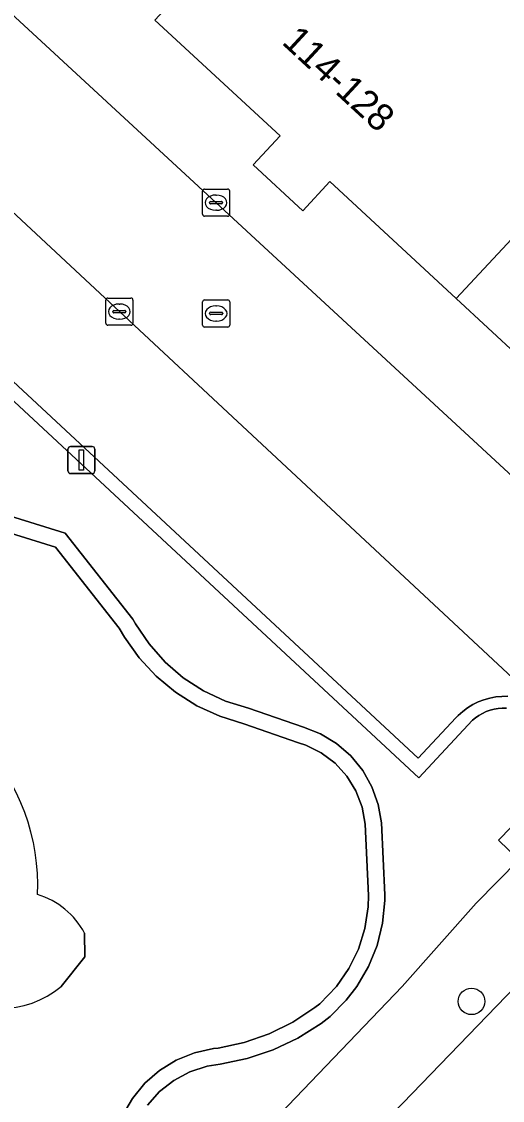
# Model space of a CAD drawing. Extents: x 159217 to 160349, y 381246 to 382172.
# Drawn here: x 159843.78 to 159861.49, y 381745.8 to 381785.53 of the extents above; entities that cross this region are included whole.
import ezdxf

# ---------------------------------------------------------------- set-up
doc = ezdxf.new("R2010")
doc.units = 0
for name, color, linetype in [('IMGEO_Boom', 7, 'Continuous'), ('IMGEO_Groenvoorziening', 7, 'Continuous'), ('IMGEO_Haag', 7, 'Continuous'), ('IMGEO_Kolk', 7, 'Continuous'), ('IMGEO_Lichtmast', 7, 'Continuous'), ('IMGEO_Pand', 7, 'Continuous'), ('IMGEO_Pand_nummerreeks', 7, 'Continuous'), ('IMGEO_Parkeervlak_open', 7, 'Continuous'), ('IMGEO_Rijbaan_lokaal_gesloten', 7, 'Continuous'), ('IMGEO_Rijbaan_lokaal_open', 7, 'Continuous'), ('IMGEO_Rioolput', 7, 'Continuous'), ('IMGEO_Voetpad_halfverhard', 7, 'Continuous'), ('IMGEO_Voetpad_open', 7, 'Continuous')]:
    doc.layers.add(name, color=color, linetype=linetype)

msp = doc.modelspace()

# ---------------------------------------------------------------- linework, layer by layer
at = {"layer": 'IMGEO_Boom'}
msp.add_circle((159860.355, 381749.447), 0.489, dxfattribs=at)
at = {"layer": 'IMGEO_Groenvoorziening'}
for points in [[(159861.641, 381760.247), (159861.488, 381760.248), (159861.335, 381760.235), (159861.185, 381760.209), (159861.037, 381760.17), (159860.893, 381760.117), (159860.755, 381760.052), (159860.623, 381759.975), (159860.499, 381759.887), (159860.395, 381759.799), (159858.417, 381757.678), (159829.839, 381784.238)], [(159848.422, 381745.62), (159848.866, 381746.122), (159849.392, 381746.537), (159849.984, 381746.851), (159850.622, 381747.055), (159851.095, 381747.13), (159852.085, 381747.338), (159853.043, 381747.661), (159853.956, 381748.096), (159854.811, 381748.635), (159855.152, 381748.893), (159855.743, 381749.491), (159856.133, 381750), (159856.558, 381750.727), (159856.874, 381751.506), (159857.077, 381752.322), (159857.162, 381753.159), (159857.164, 381753.365), (159857.033, 381756.016), (159856.919, 381756.699), (159856.688, 381757.352), (159856.349, 381757.955), (159855.911, 381758.491), (159855.387, 381758.944), (159854.792, 381759.299), (159854.166, 381759.541), (159852.136, 381760.243), (159851.289, 381760.508), (159850.485, 381760.886), (159849.739, 381761.367), (159849.065, 381761.945), (159848.476, 381762.609), (159847.98, 381763.346), (159847.88, 381763.526), (159845.383, 381766.692), (159839.65, 381768.475)], [(159839.65, 381768.475), (159845.383, 381766.692), (159847.88, 381763.526), (159847.98, 381763.346), (159848.476, 381762.609), (159849.065, 381761.945), (159849.739, 381761.367), (159850.485, 381760.886), (159851.289, 381760.508), (159852.136, 381760.243), (159854.166, 381759.541), (159854.792, 381759.299), (159855.387, 381758.944), (159855.911, 381758.491), (159856.349, 381757.955), (159856.688, 381757.352), (159856.919, 381756.699), (159857.033, 381756.016), (159857.164, 381753.365), (159857.162, 381753.159), (159857.077, 381752.322), (159856.874, 381751.506), (159856.558, 381750.727), (159856.133, 381750), (159855.743, 381749.491), (159855.152, 381748.893), (159854.811, 381748.635), (159853.956, 381748.096), (159853.043, 381747.661), (159852.085, 381747.338), (159851.095, 381747.13), (159850.622, 381747.055), (159849.984, 381746.851), (159849.392, 381746.537), (159848.866, 381746.122), (159848.422, 381745.62)], [(159847.504, 381745.245), (159847.864, 381745.87), (159848.322, 381746.428), (159848.866, 381746.902), (159849.48, 381747.279), (159850.149, 381747.55), (159850.854, 381747.706), (159851.022, 381747.725), (159851.976, 381747.93), (159852.897, 381748.25), (159853.772, 381748.68), (159854.588, 381749.215), (159854.767, 381749.353), (159855.386, 381750), (159855.839, 381750.657), (159856.189, 381751.373), (159856.427, 381752.135), (159856.548, 381752.923), (159856.564, 381753.349), (159856.434, 381755.977), (159856.323, 381756.605), (159856.096, 381757.202), (159855.762, 381757.745), (159855.332, 381758.217), (159854.822, 381758.6), (159854.249, 381758.881), (159853.985, 381758.969), (159851.967, 381759.666), (159851.082, 381759.945), (159850.241, 381760.335), (159849.456, 381760.831), (159848.743, 381761.424), (159848.111, 381762.103), (159847.573, 381762.859), (159847.377, 381763.195), (159845.027, 381766.174), (159839.528, 381767.885)], [(159839.528, 381767.885), (159845.027, 381766.174), (159847.377, 381763.195), (159847.573, 381762.859), (159848.111, 381762.103), (159848.743, 381761.424), (159849.456, 381760.831), (159850.241, 381760.335), (159851.082, 381759.945), (159851.967, 381759.666), (159853.985, 381758.969), (159854.249, 381758.881), (159854.822, 381758.6), (159855.332, 381758.217), (159855.762, 381757.745), (159856.096, 381757.202), (159856.323, 381756.605), (159856.434, 381755.977), (159856.564, 381753.349), (159856.548, 381752.923), (159856.427, 381752.135), (159856.189, 381751.373), (159855.839, 381750.657), (159855.386, 381750), (159854.767, 381749.353), (159854.588, 381749.215), (159853.772, 381748.68), (159852.897, 381748.25), (159851.976, 381747.93), (159851.022, 381747.725), (159850.854, 381747.706), (159850.149, 381747.55), (159849.48, 381747.279), (159848.866, 381746.902), (159848.322, 381746.428), (159847.864, 381745.87), (159847.504, 381745.245)], [(159836.763, 381728.06), (159857.805, 381750), (159860.522, 381753.058), (159862.102, 381754.657), (159861.343, 381755.378), (159864.2, 381758.302)], [(159846.104, 381751.957), (159846.111, 381751.081), (159845.243, 381750)]]:
    msp.add_lwpolyline(points, dxfattribs=at)
for centre, radius, start, end in [((159836.67, 381753.73), 7.707, 357.3917, 89.0761), ((159843.535, 381750.592), 2.909, 27.9855, 73.3386), ((159842.981, 381752.704), 3.525, 230.0948, 309.9052)]:
    msp.add_arc(centre, radius, start, end, dxfattribs=at)
at = {"layer": 'IMGEO_Haag'}
for points in [[(159848.422, 381745.62), (159848.866, 381746.122), (159849.392, 381746.537), (159849.984, 381746.851), (159850.622, 381747.055), (159851.095, 381747.13), (159852.085, 381747.338), (159853.043, 381747.661), (159853.956, 381748.096), (159854.811, 381748.635), (159855.152, 381748.893), (159855.743, 381749.491), (159856.133, 381750), (159856.558, 381750.727), (159856.874, 381751.506), (159857.077, 381752.322), (159857.162, 381753.159), (159857.164, 381753.365), (159857.033, 381756.016), (159856.919, 381756.699), (159856.688, 381757.352), (159856.349, 381757.955), (159855.911, 381758.491), (159855.387, 381758.944), (159854.792, 381759.299), (159854.166, 381759.541), (159852.136, 381760.243), (159851.289, 381760.508), (159850.485, 381760.886), (159849.739, 381761.367), (159849.065, 381761.945), (159848.476, 381762.609), (159847.98, 381763.346), (159847.88, 381763.526), (159845.383, 381766.692), (159839.65, 381768.475)], [(159839.528, 381767.885), (159845.027, 381766.174), (159847.377, 381763.195), (159847.573, 381762.859), (159848.111, 381762.103), (159848.743, 381761.424), (159849.456, 381760.831), (159850.241, 381760.335), (159851.082, 381759.945), (159851.967, 381759.666), (159853.985, 381758.969), (159854.249, 381758.881), (159854.822, 381758.6), (159855.332, 381758.217), (159855.762, 381757.745), (159856.096, 381757.202), (159856.323, 381756.605), (159856.434, 381755.977), (159856.564, 381753.349), (159856.548, 381752.923), (159856.427, 381752.135), (159856.189, 381751.373), (159855.839, 381750.657), (159855.386, 381750), (159854.767, 381749.353), (159854.588, 381749.215), (159853.772, 381748.68), (159852.897, 381748.25), (159851.976, 381747.93), (159851.022, 381747.725), (159850.854, 381747.706), (159850.149, 381747.55), (159849.48, 381747.279), (159848.866, 381746.902), (159848.322, 381746.428), (159847.864, 381745.87), (159847.504, 381745.245)]]:
    msp.add_lwpolyline(points, dxfattribs=at)
at = {"layer": 'IMGEO_Kolk'}
for p, q in [((159850.445, 381778.437), (159850.445, 381779.289)), ((159850.52, 381779.363), (159851.372, 381779.363)), ((159850.933, 381779.143), (159850.958, 381779.143)), ((159851.446, 381779.289), (159851.446, 381778.437)), ((159850.704, 381778.857), (159850.704, 381778.869)), ((159851.142, 381778.82), (159850.744, 381778.82)), ((159850.747, 381778.906), (159851.145, 381778.906)), ((159851.188, 381778.869), (159851.188, 381778.857)), ((159851.372, 381778.363), (159850.52, 381778.363)), ((159850.956, 381778.583), (159850.931, 381778.583)), ((159846.883, 381774.424), (159846.883, 381775.276)), ((159846.958, 381775.35), (159847.81, 381775.35)), ((159847.371, 381775.13), (159847.396, 381775.13)), ((159847.884, 381775.276), (159847.884, 381774.424)), ((159847.142, 381774.844), (159847.142, 381774.856)), ((159847.58, 381774.807), (159847.182, 381774.807)), ((159847.185, 381774.893), (159847.583, 381774.893)), ((159847.626, 381774.856), (159847.626, 381774.844)), ((159847.81, 381774.35), (159846.958, 381774.35)), ((159847.394, 381774.57), (159847.369, 381774.57))]:
    msp.add_line(p, q, dxfattribs=at)
for points in [[(159850.445, 381778.437), (159850.445, 381779.289)], [(159850.52, 381779.363), (159851.372, 381779.363)], [(159851.446, 381779.289), (159851.446, 381778.437)], [(159851.372, 381778.363), (159850.52, 381778.363)], [(159846.883, 381774.424), (159846.883, 381775.276)], [(159846.958, 381775.35), (159847.81, 381775.35)], [(159847.884, 381775.276), (159847.884, 381774.424)], [(159847.81, 381774.35), (159846.958, 381774.35)]]:
    msp.add_lwpolyline(points, dxfattribs=at)
for centre, radius, start, end in [((159850.522, 381779.287), 0.0765, 91.552, 178.448), ((159850.522, 381779.287), 0.0765, 91.552, 178.448), ((159851.37, 381779.287), 0.0765, 1.552, 88.448), ((159851.37, 381779.287), 0.0765, 1.552, 88.448), ((159850.744, 381778.866), 0.0403, 85.8775, 175.7526), ((159850.741, 381778.856), 0.0366, 178.938, 274.7102), ((159851.145, 381778.863), 0.043, 264.8664, 352.4533), ((159851.149, 381778.868), 0.0386, 1.7309, 96.639), ((159850.522, 381778.439), 0.0765, 181.552, 268.448), ((159850.522, 381778.439), 0.0765, 181.552, 268.448), ((159851.37, 381778.439), 0.0765, 271.552, 358.448), ((159851.37, 381778.439), 0.0765, 271.552, 358.448), ((159846.96, 381775.274), 0.0765, 91.552, 178.448), ((159846.96, 381775.274), 0.0765, 91.552, 178.448), ((159847.808, 381775.274), 0.0765, 1.552, 88.448), ((159847.808, 381775.274), 0.0765, 1.552, 88.448), ((159847.182, 381774.853), 0.0403, 85.8775, 175.7526), ((159847.179, 381774.843), 0.0366, 178.938, 274.7102), ((159847.583, 381774.85), 0.043, 264.8664, 352.4533), ((159847.587, 381774.855), 0.0386, 1.7309, 96.639), ((159846.96, 381774.426), 0.0765, 181.552, 268.448), ((159846.96, 381774.426), 0.0765, 181.552, 268.448), ((159847.808, 381774.426), 0.0765, 271.552, 358.448), ((159847.808, 381774.426), 0.0765, 271.552, 358.448)]:
    msp.add_arc(centre, radius, start, end, dxfattribs=at)
for centre, major_axis, ratio, start_param, end_param in [((159850.932, 381778.863), (-0.387, 0.002), 0.722429, 4.712389, 7.853982), ((159850.957, 381778.863), (-0.39, 0.002), 0.717154, 1.570796, 4.712389), ((159847.37, 381774.85), (-0.387, 0.002), 0.722429, 4.712389, 7.853982), ((159847.395, 381774.85), (-0.39, 0.002), 0.717154, 1.570796, 4.712389)]:
    msp.add_ellipse(centre, major_axis=major_axis, ratio=ratio, start_param=start_param, end_param=end_param, dxfattribs=at)
at = {"layer": 'IMGEO_Lichtmast'}
for p, q in [((159845.489, 381768.983), (159845.489, 381769.783)), ((159845.489, 381769.783), (159845.489, 381768.983)), ((159845.589, 381769.883), (159846.379, 381769.883)), ((159846.379, 381769.883), (159845.589, 381769.883)), ((159846.479, 381769.783), (159846.479, 381768.983)), ((159846.479, 381768.983), (159846.479, 381769.783)), ((159846.379, 381768.883), (159845.589, 381768.883)), ((159845.589, 381768.883), (159846.379, 381768.883))]:
    msp.add_line(p, q, dxfattribs=at)
msp.add_lwpolyline([(159845.909, 381769.758), (159846.059, 381769.758), (159846.059, 381769.008), (159845.909, 381769.008), (159845.909, 381769.758)], dxfattribs=at)
for centre, start, end in [((159845.589, 381769.783), 90, 180), ((159845.589, 381769.783), 90, 180), ((159846.379, 381769.783), 0, 90), ((159846.379, 381769.783), 360, 90), ((159845.589, 381768.983), 180, 270), ((159845.589, 381768.983), 180, 270), ((159846.379, 381768.983), 270, 0), ((159846.379, 381768.983), 270, 0)]:
    msp.add_arc(centre, 0.1, start, end, dxfattribs=at)
at = {"layer": 'IMGEO_Pand'}
for points in [[(159848.695, 381785.59), (159853.302, 381781.33), (159852.311, 381780.259), (159854.139, 381778.568), (159855.131, 381779.641), (159859.793, 381775.329), (159867.103, 381783.184), (159856.038, 381793.481)], [(159859.793, 381775.329), (159864.456, 381771.017), (159863.465, 381769.945), (159865.123, 381768.411), (159866.115, 381769.484), (159870.855, 381765.1), (159870.993, 381765.25), (159878.104, 381772.948), (159867.103, 381783.184)]]:
    msp.add_lwpolyline(points, close=True, dxfattribs=at)
at = {"layer": 'IMGEO_Parkeervlak_open'}
for points in [[(159863.307, 381760.012), (159835.985, 381785.476)], [(159834.334, 381780.765), (159858.391, 381758.406), (159859.774, 381759.888), (159859.863, 381759.978), (159860.03, 381760.127), (159860.21, 381760.259), (159860.401, 381760.376), (159860.601, 381760.474), (159860.81, 381760.554), (159861.025, 381760.616), (159861.244, 381760.658), (159861.466, 381760.68), (159861.69, 381760.682)]]:
    msp.add_lwpolyline(points, dxfattribs=at)
at = {"layer": 'IMGEO_Rijbaan_lokaal_gesloten'}
msp.add_lwpolyline([(159845.193, 381723.719), (159887.563, 381767.762), (159883.179, 381772.041), (159880.608, 381769.436), (159872.007, 381760.464), (159867.295, 381755.549), (159861.976, 381750), (159851.927, 381739.596)], dxfattribs=at)
at = {"layer": 'IMGEO_Rijbaan_lokaal_open'}
for points in [[(159869.262, 381761.943), (159836.624, 381792.091), (159834.612, 381793.898), (159834.039, 381794.273), (159833.435, 381794.596), (159832.804, 381794.863), (159832.152, 381795.073), (159831.484, 381795.224), (159830.805, 381795.314), (159830.121, 381795.344), (159829.437, 381795.312), (159828.758, 381795.219), (159828.09, 381795.066), (159827.439, 381794.854), (159826.809, 381794.585), (159826.206, 381794.26), (159825.925, 381794.084), (159791.101, 381766.789)], [(159802.563, 381768.781), (159825.78, 381786.951), (159826.599, 381787.592), (159826.648, 381787.626), (159827.119, 381787.917), (159827.614, 381788.164), (159828.129, 381788.366), (159828.66, 381788.522), (159829.202, 381788.629), (159829.752, 381788.688), (159830.306, 381788.697), (159830.857, 381788.657), (159831.403, 381788.568), (159831.939, 381788.43), (159832.461, 381788.245), (159832.963, 381788.014), (159833.443, 381787.739), (159833.897, 381787.422), (159835.985, 381785.476), (159863.307, 381760.012)]]:
    msp.add_lwpolyline(points, dxfattribs=at)
at = {"layer": 'IMGEO_Rioolput'}
for p, q in [((159850.448, 381774.356), (159850.448, 381775.208)), ((159850.523, 381775.282), (159851.375, 381775.282)), ((159851.449, 381775.208), (159851.449, 381774.356)), ((159850.707, 381774.776), (159850.707, 381774.788)), ((159851.145, 381774.739), (159850.747, 381774.739)), ((159850.75, 381774.825), (159851.148, 381774.825)), ((159850.936, 381775.062), (159850.961, 381775.062)), ((159851.191, 381774.788), (159851.191, 381774.776)), ((159851.375, 381774.282), (159850.523, 381774.282)), ((159850.959, 381774.502), (159850.934, 381774.502))]:
    msp.add_line(p, q, dxfattribs=at)
for points in [[(159850.448, 381774.356), (159850.448, 381775.208)], [(159850.523, 381775.282), (159851.375, 381775.282)], [(159851.449, 381775.208), (159851.449, 381774.356)], [(159851.375, 381774.282), (159850.523, 381774.282)]]:
    msp.add_lwpolyline(points, dxfattribs=at)
for centre, radius, start, end in [((159850.525, 381775.206), 0.0765, 91.552, 178.448), ((159850.525, 381775.206), 0.0765, 91.552, 178.448), ((159851.373, 381775.206), 0.0765, 1.552, 88.448), ((159851.373, 381775.206), 0.0765, 1.552, 88.448), ((159850.747, 381774.785), 0.0403, 85.8775, 175.7526), ((159850.744, 381774.775), 0.0366, 178.938, 274.7102), ((159851.148, 381774.782), 0.043, 264.8664, 352.4533), ((159851.152, 381774.787), 0.0386, 1.7309, 96.639), ((159850.525, 381774.358), 0.0765, 181.552, 268.448), ((159850.525, 381774.358), 0.0765, 181.552, 268.448), ((159851.373, 381774.358), 0.0765, 271.552, 358.448), ((159851.373, 381774.358), 0.0765, 271.552, 358.448)]:
    msp.add_arc(centre, radius, start, end, dxfattribs=at)
for centre, major_axis, ratio, start_param, end_param in [((159850.935, 381774.782), (-0.387, 0.002), 0.722429, 4.712389, 7.853982), ((159850.96, 381774.782), (-0.39, 0.002), 0.717154, 1.570796, 4.712389)]:
    msp.add_ellipse(centre, major_axis=major_axis, ratio=ratio, start_param=start_param, end_param=end_param, dxfattribs=at)
at = {"layer": 'IMGEO_Voetpad_halfverhard'}
msp.add_lwpolyline([(159845.243, 381750), (159846.111, 381751.081), (159846.104, 381751.957)], dxfattribs=at)
for centre, radius, start, end in [((159836.67, 381753.73), 7.707, 357.3917, 89.0761), ((159843.535, 381750.592), 2.909, 27.9855, 73.3386), ((159842.981, 381752.704), 3.525, 230.0948, 309.9052)]:
    msp.add_arc(centre, radius, start, end, dxfattribs=at)
at = {"layer": 'IMGEO_Voetpad_open'}
for points in [[(159791.101, 381766.789), (159825.925, 381794.084), (159826.206, 381794.26), (159826.809, 381794.585), (159827.439, 381794.854), (159828.09, 381795.066), (159828.758, 381795.219), (159829.437, 381795.312), (159830.121, 381795.344), (159830.805, 381795.314), (159831.484, 381795.224), (159832.152, 381795.073), (159832.804, 381794.863), (159833.435, 381794.596), (159834.039, 381794.273), (159834.612, 381793.898), (159836.624, 381792.091), (159869.262, 381761.943)], [(159825.209, 381785.654), (159825.226, 381785.521), (159825.254, 381785.39), (159825.294, 381785.262), (159825.345, 381785.138), (159825.407, 381785.019), (159825.479, 381784.906), (159825.531, 381784.836), (159827.49, 381782.374), (159829.839, 381784.238), (159858.417, 381757.678), (159860.395, 381759.799), (159860.499, 381759.887), (159860.623, 381759.975), (159860.755, 381760.052), (159860.893, 381760.117), (159861.037, 381760.17), (159861.185, 381760.209), (159861.335, 381760.235), (159861.488, 381760.248), (159861.641, 381760.247)], [(159864.456, 381771.017), (159859.793, 381775.329), (159855.131, 381779.641), (159854.139, 381778.568), (159852.311, 381780.259), (159853.302, 381781.33), (159848.695, 381785.59)], [(159861.69, 381760.682), (159861.466, 381760.68), (159861.244, 381760.658), (159861.025, 381760.616), (159860.81, 381760.554), (159860.601, 381760.474), (159860.401, 381760.376), (159860.21, 381760.259), (159860.03, 381760.127), (159859.863, 381759.978), (159859.774, 381759.888), (159858.391, 381758.406), (159834.334, 381780.765)], [(159851.927, 381739.596), (159861.976, 381750), (159867.295, 381755.549), (159866.935, 381755.895), (159865.095, 381757.601), (159864.2, 381758.302), (159861.343, 381755.378), (159862.102, 381754.657), (159860.522, 381753.058), (159857.805, 381750), (159836.763, 381728.06)]]:
    msp.add_lwpolyline(points, dxfattribs=at)

# ---------------------------------------------------------------- texts
at = {"layer": 'IMGEO_Pand_nummerreeks'}
msp.add_text('114-128', height=1, rotation=317.2441, dxfattribs=at).set_placement((159853.332, 381784.735))

doc.saveas('drawing.dxf')
